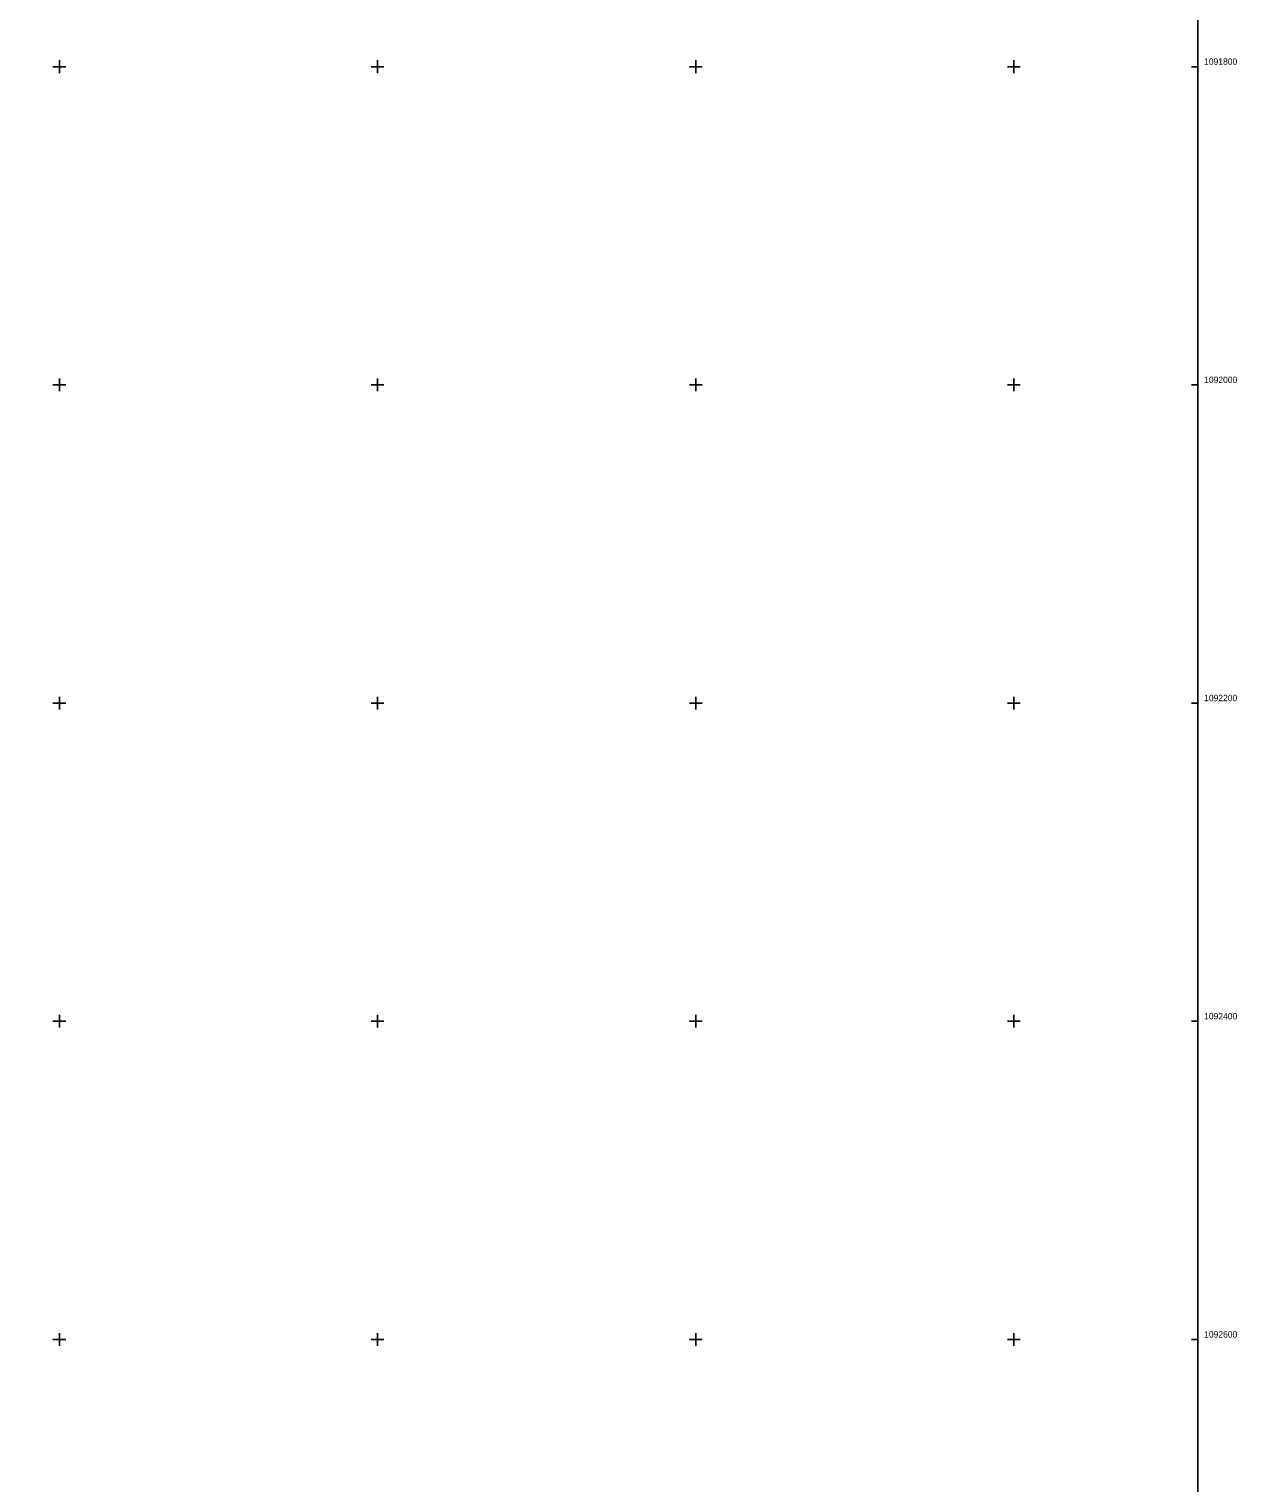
# Model space of a CAD drawing. Extents: x -567962 to -566460, y -1093720 to -1089838.
# Drawn here: x -567219 to -566460, y -1092690 to -1091776 of the extents above; entities that cross this region are included whole.
import ezdxf

# ---------------------------------------------------------------- set-up
doc = ezdxf.new("R2010")
doc.units = 0
doc.layers.add('ctvercova_sit', color=7, linetype='Continuous')
doc.layers.add('ram', color=7, linetype='Continuous')

msp = doc.modelspace()

# ---------------------------------------------------------------- linework, layer by layer
at = {"layer": 'ctvercova_sit'}
for points in [[(-567200, -1091796), (-567200, -1091804)], [(-567000, -1091796), (-567000, -1091804)], [(-566800, -1091796), (-566800, -1091804)], [(-566600, -1091796), (-566600, -1091804)], [(-567196, -1091800), (-567204, -1091800)], [(-566996, -1091800), (-567004, -1091800)], [(-566796, -1091800), (-566804, -1091800)], [(-566596, -1091800), (-566604, -1091800)], [(-566488.41, -1091800), (-566484.41, -1091800)], [(-567200, -1091996), (-567200, -1092004)], [(-567000, -1091996), (-567000, -1092004)], [(-566800, -1091996), (-566800, -1092004)], [(-566600, -1091996), (-566600, -1092004)], [(-567196, -1092000), (-567204, -1092000)], [(-566996, -1092000), (-567004, -1092000)], [(-566796, -1092000), (-566804, -1092000)], [(-566596, -1092000), (-566604, -1092000)], [(-566488.41, -1092000), (-566484.41, -1092000)], [(-567196, -1092200), (-567204, -1092200)], [(-567200, -1092196), (-567200, -1092204)], [(-566996, -1092200), (-567004, -1092200)], [(-567000, -1092196), (-567000, -1092204)], [(-566796, -1092200), (-566804, -1092200)], [(-566800, -1092196), (-566800, -1092204)], [(-566596, -1092200), (-566604, -1092200)], [(-566600, -1092196), (-566600, -1092204)], [(-566488.41, -1092200), (-566484.41, -1092200)], [(-567196, -1092400), (-567204, -1092400)], [(-567200, -1092396), (-567200, -1092404)], [(-566996, -1092400), (-567004, -1092400)], [(-567000, -1092396), (-567000, -1092404)], [(-566796, -1092400), (-566804, -1092400)], [(-566800, -1092396), (-566800, -1092404)], [(-566596, -1092400), (-566604, -1092400)], [(-566600, -1092396), (-566600, -1092404)], [(-566488.41, -1092400), (-566484.41, -1092400)], [(-567196, -1092600), (-567204, -1092600)], [(-567200, -1092596), (-567200, -1092604)], [(-566996, -1092600), (-567004, -1092600)], [(-567000, -1092596), (-567000, -1092604)], [(-566796, -1092600), (-566804, -1092600)], [(-566800, -1092596), (-566800, -1092604)], [(-566596, -1092600), (-566604, -1092600)], [(-566600, -1092596), (-566600, -1092604)], [(-566488.41, -1092600), (-566484.41, -1092600)]]:
    msp.add_lwpolyline(points, dxfattribs=at)
at = {"layer": 'ram'}
msp.add_lwpolyline([(-567933.74, -1093697), (-567933.74, -1089860.94), (-566484.41, -1089860.94), (-566484.41, -1093697), (-567933.74, -1093697)], dxfattribs=at)

# ---------------------------------------------------------------- texts
at = {"layer": 'ctvercova_sit'}
for s, p in [('1091800 ', (-566480.41, -1091798.8)), ('1092000 ', (-566480.41, -1091998.8)), ('1092200 ', (-566480.41, -1092198.8)), ('1092400 ', (-566480.41, -1092398.8)), ('1092600 ', (-566480.41, -1092598.8))]:
    msp.add_text(s, height=4, dxfattribs=at).set_placement(p)

doc.saveas('drawing.dxf')
